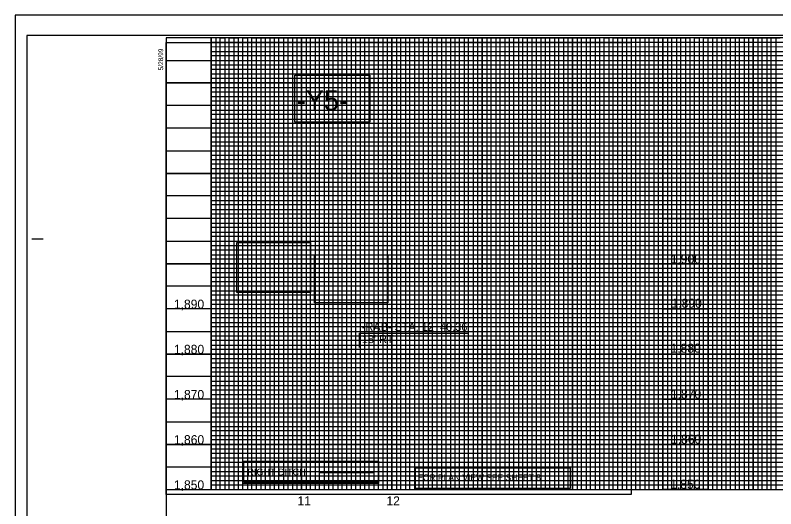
# Model space of a CAD drawing. Extents: x 557032 to 558716, y 525869 to 526969.
# Drawn here: x 557032 to 557874, y 526423 to 526969 of the extents above; entities that cross this region are included whole.
import ezdxf

# ---------------------------------------------------------------- set-up
doc = ezdxf.new("R2010")
doc.units = 0
for name, color, linetype in [('Exist Vertical Profile Horizontal Axis Label Major', 7, 'Continuous'), ('Exist Vertical Profile Vertical Axis Label', 7, 'Continuous'), ('Old_Level_63', 7, 'Continuous'), ('Prop Grid Mask', 7, 'Continuous'), ('Prop PFL Ditch Label CELL', 7, 'Continuous'), ('Prop Vertical Profile Curve Label', 7, 'Continuous'), ('Prop Vertical Profile Grade Label', 7, 'Continuous'), ('Prop VPI Label', 7, 'Continuous'), ('Scratch_Level_5', 7, 'Continuous'), ('Sheet Cutting Line CELL', 7, 'Continuous'), ('Sheet DOT Grid CELL', 7, 'Continuous'), ('Sheet Layout Profile Border Port 1', 7, 'Continuous'), ('Sheet Plot Border Inside CELL', 7, 'Continuous'), ('Sheet Plot Border Outside CELL', 7, 'Continuous'), ('Sheet Profile CELL', 7, 'Continuous'), ('Sheet Profile Grid Major CELL', 7, 'Continuous'), ('Sheet Profile Grid Middle CELL', 7, 'Continuous'), ('Sheet Profile Grid Minor CELL', 7, 'Continuous')]:
    doc.layers.add(name, color=color, linetype=linetype)

msp = doc.modelspace()

# ---------------------------------------------------------------- linework, layer by layer
at = {"layer": 'Old_Level_63'}
msp.add_lwpolyline([(557749.45, 526744.22), (557799.45, 526744.22), (557799.45, 526444.22), (557749.45, 526444.22)], close=True, dxfattribs=at)
at = {"layer": 'Prop Grid Mask'}
msp.add_lwpolyline([(557284.52, 526475.87), (557434.52, 526475.87), (557434.52, 526450.87), (557284.52, 526450.87)], close=True, dxfattribs=at)
at = {"layer": 'Prop PFL Ditch Label CELL'}
for p, q in [((557284.52, 526460.87), (557284.52, 526460.87)), ((557370.07, 526463.22), (557430.07, 526463.22))]:
    msp.add_line(p, q, dxfattribs=at)
at = {"layer": 'Prop Vertical Profile Curve Label'}
for points in [[(557341.96, 526902.85), (557424.96, 526902.85), (557424.96, 526850.91), (557341.96, 526850.91)], [(557341.96, 526902.85), (557424.96, 526902.85), (557424.96, 526850.91), (557341.96, 526850.91)], [(557277.74, 526717.66), (557359.2, 526717.66), (557359.2, 526662.47), (557277.74, 526662.47)], [(557363.75, 526703.99), (557445.1, 526703.99), (557445.1, 526651.05), (557363.75, 526651.05)]]:
    msp.add_lwpolyline(points, close=True, dxfattribs=at)
at = {"layer": 'Prop VPI Label'}
for p, q in [((557413.6, 526601.36), (557413.68, 526617.44)), ((557413.68, 526617.44), (557533.97, 526617.21))]:
    msp.add_line(p, q, dxfattribs=at)
for points in [[(557341.96, 526902.85), (557424.45, 526902.85), (557424.45, 526850.91), (557341.96, 526850.91)], [(557285.37, 526475.2), (557434.1, 526475.2), (557434.1, 526452.36), (557285.37, 526452.36)], [(557475.65, 526468.46), (557646.79, 526468.46), (557646.79, 526445.55), (557475.65, 526445.55)], [(557475.65, 526468.46), (557646.79, 526468.46), (557646.79, 526445.55), (557475.65, 526445.55)]]:
    msp.add_lwpolyline(points, close=True, dxfattribs=at)
at = {"layer": 'Scratch_Level_5'}
msp.add_lwpolyline([(557199.45, 526938.89), (557714.45, 526938.89), (557714.5, 526438.89), (557199.5, 526438.89)], close=True, dxfattribs=at)
at = {"layer": 'Sheet Cutting Line CELL'}
for p, q in [((558716.45, 526969.22), (557032.45, 526969.22)), ((557032.45, 526969.22), (557032.45, 525869.22))]:
    msp.add_line(p, q, dxfattribs=at)
at = {"layer": 'Sheet DOT Grid CELL'}
for p, q in [((557249.45, 526444.22), (557249.45, 526944.22)), ((557299.45, 526444.22), (557299.45, 526944.22)), ((557349.45, 526444.22), (557349.45, 526944.22)), ((557399.45, 526444.22), (557399.45, 526944.22)), ((557449.45, 526444.22), (557449.45, 526944.22)), ((557499.45, 526444.22), (557499.45, 526944.22)), ((557549.45, 526444.22), (557549.45, 526944.22)), ((557599.45, 526444.22), (557599.45, 526944.22)), ((557649.45, 526444.22), (557649.45, 526944.22)), ((557699.45, 526444.22), (557699.45, 526944.22)), ((557749.45, 526444.22), (557749.45, 526944.22)), ((557799.45, 526444.22), (557799.45, 526944.22)), ((557849.45, 526444.22), (557849.45, 526944.22)), ((558499.4, 526894.22), (557199.45, 526894.22)), ((558499.4, 526844.22), (557199.45, 526844.22)), ((558499.45, 526794.22), (557199.45, 526794.22)), ((558699.45, 526694.22), (557199.45, 526694.22)), ((558699.45, 526644.22), (557199.45, 526644.22)), ((558699.45, 526594.22), (557199.45, 526594.22)), ((558699.45, 526544.22), (557199.45, 526544.22)), ((558699.45, 526494.22), (557199.45, 526494.22))]:
    msp.add_line(p, q, dxfattribs=at)
at = {"layer": 'Sheet Layout Profile Border Port 1'}
msp.add_lwpolyline([(557249.45, 526783.17), (557249.45, 526444.22), (558649.45, 526444.22), (558649.45, 526783.17)], dxfattribs=at)
at = {"layer": 'Sheet Plot Border Inside CELL'}
msp.add_lwpolyline([(557045.45, 525891.67), (558711.95, 525891.67), (558711.95, 526946.77), (557045.45, 526946.77)], close=True, dxfattribs=at)
at = {"layer": 'Sheet Plot Border Outside CELL'}
msp.add_lwpolyline([(557032.45, 525869.22), (558716.45, 525869.22), (558716.45, 526969.22), (557032.45, 526969.22)], close=True, dxfattribs=at)
at = {"layer": 'Sheet Profile CELL'}
for p, q in [((557050.95, 526721.72), (557063.45, 526721.72)), ((557199.45, 526444.22), (558699.45, 526444.22))]:
    msp.add_line(p, q, dxfattribs=at)
msp.add_lwpolyline([(558699.45, 526944.22), (557199.45, 526944.22), (557199.45, 525894.22), (558699.45, 525894.22)], close=True, dxfattribs=at)
at = {"layer": 'Sheet Profile Grid Major CELL'}
for p, q in [((557749.45, 526694.22), (557799.45, 526694.22)), ((557749.45, 526644.22), (557799.45, 526644.22)), ((557749.45, 526594.22), (557799.45, 526594.22)), ((557749.45, 526544.22), (557799.45, 526544.22)), ((557799.45, 526544.22), (557799.45, 526544.22)), ((557749.45, 526494.22), (557799.45, 526494.22))]:
    msp.add_line(p, q, dxfattribs=at)
for points in [[(557249.45, 526944.22), (557249.45, 526444.22), (557299.45, 526444.22), (557299.45, 526944.22), (557349.45, 526944.22), (557349.45, 526444.22), (557399.45, 526444.22), (557399.45, 526944.22), (557449.45, 526944.22), (557449.45, 526444.22), (557499.45, 526444.22), (557499.45, 526944.22), (557549.45, 526944.22), (557549.45, 526444.22), (557599.45, 526444.22), (557599.45, 526944.22), (557649.45, 526944.22), (557649.45, 526444.22), (557699.45, 526444.22), (557699.45, 526944.22), (557749.45, 526944.22), (557749.45, 526444.22), (557799.45, 526444.22), (557799.45, 526944.22), (557849.45, 526944.22), (557849.45, 526444.22), (557899.45, 526444.22)], [(557199.45, 526894.22), (558499.45, 526894.22)], [(558499.45, 526844.22), (557199.45, 526844.22), (557199.45, 526794.22), (558499.45, 526794.22)], [(558699.45, 526744.22), (557199.45, 526744.22), (557199.45, 526694.22), (558699.45, 526694.22)], [(558699.45, 526644.22), (557199.45, 526644.22), (557199.45, 526594.22), (558699.45, 526594.22)], [(558699.45, 526544.22), (557199.45, 526544.22), (557199.45, 526544.22), (557199.45, 526494.22), (558699.45, 526494.22)]]:
    msp.add_lwpolyline(points, dxfattribs=at)
msp.add_lwpolyline([(557749.45, 526444.22), (557799.45, 526444.22), (557799.45, 526744.22), (557749.45, 526744.22)], close=True, dxfattribs=at)
at = {"layer": 'Sheet Profile Grid Middle CELL'}
msp.add_line((557199.45, 526919.22), (558499.4, 526919.22), dxfattribs=at)
for points in [[(557274.45, 526944.22), (557274.45, 526444.22), (557324.45, 526444.22), (557324.45, 526944.22), (557374.45, 526944.22), (557374.45, 526444.22), (557424.45, 526444.22), (557424.45, 526944.22), (557474.45, 526944.22), (557474.45, 526444.22), (557524.45, 526444.22), (557524.45, 526944.22), (557574.45, 526944.22), (557574.45, 526444.22), (557624.45, 526444.22), (557624.45, 526944.22), (557674.45, 526944.22), (557674.45, 526444.22), (557724.45, 526444.22), (557724.45, 526944.22), (557774.45, 526944.22), (557774.45, 526444.22), (557824.45, 526444.22), (557824.45, 526444.22), (557824.45, 526944.22), (557874.45, 526944.22), (557874.45, 526444.22), (557924.45, 526444.22)], [(558499.45, 526869.22), (557199.45, 526869.22), (557199.45, 526819.22), (558499.45, 526819.22)], [(558699.45, 526769.22), (557199.45, 526769.22), (557199.45, 526719.22), (558524.45, 526719.22)], [(558699.45, 526669.22), (557199.45, 526669.22), (557199.45, 526619.22), (558699.45, 526619.22)], [(558699.45, 526569.22), (557199.45, 526569.22), (557199.45, 526519.22), (558699.45, 526519.22)], [(558699.45, 526469.22), (557199.45, 526469.22)]]:
    msp.add_lwpolyline(points, dxfattribs=at)
at = {"layer": 'Sheet Profile Grid Minor CELL'}
for p, q in [((557249.45, 526939.22), (558499.45, 526939.22)), ((557249.45, 526934.22), (557249.45, 526934.22)), ((558499.45, 526934.22), (557249.45, 526933.87)), ((557249.45, 526929.22), (558499.45, 526929.22)), ((558499.4, 526809.22), (557249.45, 526809.22)), ((558499.45, 526804.22), (557249.45, 526804.22)), ((558499.45, 526799.22), (557249.45, 526799.22)), ((557249.45, 526789.22), (558499.45, 526789.22)), ((558499.45, 526784.22), (557249.45, 526784.22)), ((557249.45, 526779.22), (558649.45, 526779.22)), ((558649.45, 526759.22), (557249.45, 526759.22)), ((557249.45, 526754.22), (558649.45, 526754.22)), ((558649.45, 526734.22), (557249.45, 526734.22)), ((557249.45, 526729.22), (558649.45, 526729.22)), ((558649.45, 526709.22), (557249.45, 526709.22)), ((557249.45, 526704.22), (558649.45, 526704.22)), ((558649.45, 526699.22), (557249.45, 526699.22)), ((557249.45, 526689.22), (558649.45, 526689.22)), ((558649.45, 526684.22), (557249.45, 526684.22)), ((557249.45, 526679.22), (558649.45, 526679.22)), ((558649.45, 526674.22), (557249.45, 526674.22)), ((557249.45, 526664.22), (558649.45, 526664.22)), ((558649.45, 526659.22), (557249.45, 526659.22)), ((557249.45, 526654.22), (558649.45, 526654.22)), ((558649.45, 526649.22), (557249.45, 526649.22)), ((557249.45, 526639.22), (558649.45, 526639.22)), ((558649.45, 526634.22), (557249.45, 526634.22)), ((557249.45, 526629.22), (558649.45, 526629.22)), ((558649.45, 526624.22), (557249.45, 526624.22)), ((557249.45, 526614.22), (558649.45, 526614.22)), ((558649.45, 526609.22), (557249.45, 526609.22)), ((557249.45, 526604.22), (558649.45, 526604.22)), ((558649.45, 526599.22), (557249.45, 526599.22)), ((557249.45, 526589.22), (558649.45, 526589.22)), ((558649.45, 526584.22), (557249.45, 526584.22)), ((557249.45, 526579.22), (558649.45, 526579.22)), ((558649.45, 526574.22), (557249.45, 526574.22)), ((557249.45, 526564.22), (558649.45, 526564.22)), ((558649.45, 526559.22), (557249.45, 526559.22)), ((558649.45, 526554.22), (557249.45, 526554.22)), ((558649.45, 526549.22), (557249.45, 526549.22)), ((557249.45, 526539.22), (558649.45, 526539.22)), ((558649.45, 526534.22), (557249.45, 526534.22)), ((557249.45, 526529.22), (558649.45, 526529.22)), ((558649.45, 526524.22), (557249.45, 526524.22)), ((557249.45, 526514.22), (558649.45, 526514.22)), ((558649.45, 526509.22), (557249.45, 526509.22)), ((557249.45, 526504.22), (558649.45, 526504.22)), ((558649.45, 526499.22), (557249.45, 526499.22)), ((557249.45, 526489.22), (558649.45, 526489.22)), ((558649.45, 526484.22), (557249.45, 526484.22)), ((557249.45, 526479.22), (558649.45, 526479.22)), ((558649.45, 526474.22), (557249.45, 526474.22)), ((557249.45, 526464.22), (558649.45, 526464.22)), ((558649.45, 526459.22), (557249.45, 526459.22)), ((557249.45, 526454.22), (558649.45, 526454.22))]:
    msp.add_line(p, q, dxfattribs=at)
for points in [[(557254.45, 526944.22), (557254.45, 526444.22), (557259.45, 526444.22), (557259.45, 526944.22), (557264.45, 526944.22), (557264.45, 526444.22), (557269.45, 526444.22), (557269.45, 526944.22), (557279.45, 526944.22), (557279.45, 526444.22), (557284.45, 526444.22), (557284.45, 526944.22), (557289.45, 526944.22), (557289.45, 526444.22), (557294.45, 526444.22), (557304.45, 526444.22), (557309.45, 526444.22), (557309.45, 526944.22), (557314.45, 526944.22), (557314.45, 526444.22), (557319.45, 526444.22), (557319.45, 526944.22), (557329.45, 526944.22), (557329.45, 526444.22), (557334.45, 526444.22), (557334.45, 526944.22), (557339.45, 526944.22), (557339.45, 526444.22), (557344.45, 526444.22), (557344.45, 526944.22), (557354.45, 526944.22), (557354.45, 526444.22), (557359.45, 526444.22), (557359.45, 526944.22), (557364.45, 526944.22), (557364.45, 526444.22), (557369.45, 526444.22), (557369.45, 526944.22), (557379.45, 526944.22), (557379.45, 526444.22), (557384.45, 526444.22), (557384.45, 526944.22), (557389.45, 526944.22), (557389.45, 526444.22), (557394.45, 526444.22), (557394.45, 526944.22), (557404.45, 526944.22), (557404.45, 526444.22), (557409.45, 526444.22), (557409.45, 526944.22), (557414.45, 526944.22), (557414.45, 526444.22), (557419.45, 526444.22), (557419.45, 526944.22), (557429.45, 526944.22), (557429.45, 526444.22), (557434.45, 526444.22), (557434.45, 526944.22), (557439.45, 526944.22), (557439.45, 526444.22), (557444.45, 526444.22), (557444.45, 526944.22), (557454.45, 526944.22), (557454.45, 526444.22), (557459.45, 526444.22), (557459.45, 526944.22), (557464.45, 526944.22), (557464.45, 526444.22)], [(557294.45, 526444.22), (557294.45, 526944.22), (557304.45, 526944.22), (557304.45, 526444.22)], [(557464.45, 526444.22), (557469.45, 526444.22), (557469.45, 526944.22), (557479.45, 526944.22), (557479.45, 526444.22), (557484.45, 526444.22), (557484.45, 526944.22), (557489.45, 526944.22), (557489.45, 526444.22), (557494.45, 526444.22), (557494.45, 526944.22), (557504.45, 526944.22), (557504.45, 526444.22), (557509.45, 526444.22), (557509.45, 526944.22), (557514.45, 526944.22), (557514.45, 526444.22), (557519.45, 526444.22), (557519.45, 526944.22), (557529.45, 526944.22), (557529.45, 526444.22), (557534.45, 526444.22), (557534.45, 526944.22), (557539.45, 526944.22), (557539.45, 526444.22), (557544.45, 526444.22), (557544.45, 526944.22), (557554.45, 526944.22), (557554.45, 526444.22), (557559.45, 526444.22), (557559.45, 526944.22), (557564.45, 526944.22), (557564.45, 526444.22), (557569.45, 526444.22), (557569.45, 526944.22), (557579.45, 526944.22), (557579.45, 526444.22), (557584.45, 526444.22), (557584.45, 526944.22), (557589.45, 526944.22), (557589.45, 526444.22), (557594.45, 526444.22), (557594.45, 526944.22), (557604.45, 526944.22), (557604.45, 526444.22), (557609.45, 526444.22), (557609.45, 526944.22), (557614.45, 526944.22), (557614.45, 526444.22), (557619.45, 526444.22), (557619.45, 526944.22), (557629.45, 526944.22), (557629.45, 526444.22), (557634.45, 526444.22), (557634.45, 526944.22), (557639.45, 526944.22), (557639.45, 526444.22), (557644.45, 526444.22), (557644.45, 526944.22), (557654.45, 526944.22), (557654.45, 526444.22), (557659.45, 526444.22), (557659.45, 526944.22), (557664.45, 526944.22), (557664.45, 526444.22), (557669.45, 526444.22), (557669.45, 526944.22), (557679.45, 526944.22), (557679.45, 526444.22), (557684.45, 526444.22), (557684.45, 526944.22), (557689.45, 526944.22), (557689.45, 526444.22), (557694.45, 526444.22), (557694.45, 526944.22), (557704.45, 526944.22), (557704.45, 526444.22), (557709.45, 526444.22), (557709.45, 526944.22), (557714.45, 526944.22), (557714.45, 526444.22), (557719.45, 526444.22), (557719.45, 526944.22), (557729.45, 526944.22), (557729.45, 526444.22), (557734.45, 526444.22), (557734.45, 526944.22), (557739.45, 526944.22), (557739.45, 526444.22), (557744.45, 526444.22), (557744.45, 526944.22), (557754.45, 526944.22), (557754.45, 526444.22), (557759.45, 526444.22), (557759.45, 526944.22), (557764.45, 526944.22), (557764.45, 526444.22), (557769.45, 526444.22), (557769.45, 526944.22), (557779.45, 526944.22)], [(557779.45, 526944.22), (557779.45, 526444.22), (557784.45, 526444.22), (557784.45, 526944.22), (557789.45, 526944.22), (557789.45, 526444.22), (557794.45, 526444.22), (557794.45, 526944.22), (557804.45, 526944.22), (557804.45, 526444.22), (557809.45, 526444.22), (557809.45, 526944.22), (557814.45, 526944.22), (557814.45, 526444.22), (557819.45, 526444.22), (557819.45, 526944.22), (557829.45, 526944.22), (557829.45, 526444.22), (557834.45, 526444.22), (557834.45, 526944.22), (557839.45, 526944.22), (557839.45, 526444.22), (557844.45, 526444.22), (557844.45, 526944.22), (557854.45, 526944.22), (557854.45, 526444.22), (557859.45, 526444.22), (557859.45, 526944.22), (557864.45, 526944.22), (557864.45, 526444.22), (557869.45, 526444.22), (557869.45, 526944.22), (557879.45, 526944.22)], [(558499.45, 526924.22), (557249.45, 526924.22), (557249.45, 526914.22), (558499.45, 526914.22)], [(558499.4, 526909.22), (557249.45, 526909.22), (557249.45, 526904.22), (558499.45, 526904.22)], [(558499.45, 526899.22), (557249.45, 526899.22), (557249.45, 526889.22), (558499.45, 526889.22)], [(558499.45, 526884.22), (557249.45, 526884.22), (557249.45, 526879.22), (558499.45, 526879.22)], [(558499.45, 526874.22), (557249.45, 526874.22), (557249.45, 526864.22), (558499.45, 526864.22)], [(558499.45, 526859.22), (557249.45, 526859.22), (557249.45, 526854.22), (558499.45, 526854.22)], [(558499.45, 526849.22), (557249.45, 526849.22), (557249.45, 526839.22), (558499.45, 526839.22)], [(558499.45, 526834.12), (557249.55, 526834.12), (557249.55, 526829.22), (558499.45, 526829.22)], [(558499.45, 526824.22), (557249.45, 526824.22), (557249.45, 526814.22), (558499.45, 526814.22)], [(558649.45, 526774.22), (557249.45, 526774.22), (557249.45, 526764.22), (558649.45, 526764.22)], [(558649.45, 526749.22), (557249.45, 526749.22), (557249.45, 526739.22), (558649.45, 526739.22)], [(558649.45, 526724.22), (557249.45, 526724.22), (557249.45, 526714.22), (558649.45, 526714.22)], [(558649.45, 526449.22), (557249.45, 526449.22)]]:
    msp.add_lwpolyline(points, dxfattribs=at)

# ---------------------------------------------------------------- texts
at = {"layer": 'Exist Vertical Profile Horizontal Axis Label Major'}
for s, p in [('11', (557344.88, 526426.75)), ('12', (557443.43, 526426.75))]:
    msp.add_text(s, height=10, dxfattribs=at).set_placement(p)
at = {"layer": 'Exist Vertical Profile Vertical Axis Label'}
for s, p in [('1,900', (557758.15, 526694.47)), ('1,890', (557208.15, 526644.46)), ('1,890', (557759.06, 526645.49)), ('1,880', (557208.15, 526594.46)), ('1,880', (557757.97, 526595.78)), ('1,870', (557208.15, 526544.46)), ('1,870', (557758.38, 526544.94)), ('1,860', (557208.15, 526494.46)), ('1,860', (557758.46, 526495.01)), ('1,850', (557208.15, 526444.46)), ('1,850', (557757.55, 526445.27))]:
    msp.add_text(s, height=10, dxfattribs=at).set_placement(p)
at = {"layer": 'Prop PFL Ditch Label CELL'}
msp.add_text('RIGHT DITCH', height=7.485, dxfattribs=at).set_placement((557289.52, 526459.97))
at = {"layer": 'Prop Vertical Profile Grade Label'}
msp.add_text('-Y5-', height=22.5, dxfattribs=at).set_placement((557344.07, 526863.71))
at = {"layer": 'Prop VPI Label'}
for s, height, p in [('-RAB- STA. 12+40.36', 9, (557416.27, 526619.83)), ("18' RT", 9, (557416.27, 526606.33)), ('FOR PLAN VIEW SEE SHEET 8', 7, (557478.08, 526454.11))]:
    msp.add_text(s, height=height, dxfattribs=at).set_placement(p)
at = {"layer": 'Sheet Profile CELL'}
msp.add_text('5/28/99', height=5.25, rotation=90, dxfattribs=at).set_placement((557196.22, 526908.13))

doc.saveas('drawing.dxf')
